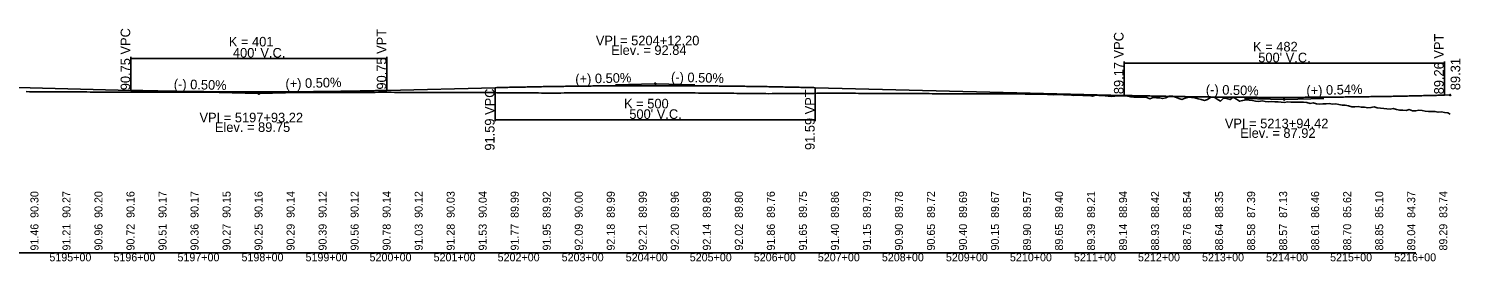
# Model space of a CAD drawing. Extents: x 2121671 to 2169879, y 557274 to 599957.
# Drawn here: x 2149002 to 2151237, y 582173 to 582537 of the extents above; entities that cross this region are included whole.
import ezdxf

# ---------------------------------------------------------------- set-up
doc = ezdxf.new("R2010")
doc.units = 0
for name, color, linetype in [('RD_DDB_GradeTX', 7, 'Continuous'), ('RD_DDB_Profile_EX', 7, 'Continuous'), ('RD_DDB_Profile_Lbl', 7, 'Continuous'), ('RD_DDB_Profile_PR', 7, 'Continuous'), ('RD_DDB_StaTX', 7, 'Continuous'), ('RD_DDB_StripGrade', 7, 'Continuous'), ('RD_DDB_VCLbl', 7, 'Continuous'), ('RD_GPK_Profile_Cell', 7, 'Continuous')]:
    doc.layers.add(name, color=color, linetype=linetype)

msp = doc.modelspace()

# ---------------------------------------------------------------- linework, layer by layer
at = {"layer": 'RD_DDB_GradeTX'}
for p, q in [((2149299.2, 582437.1), (2149360.2, 582435.6)), ((2149423.1, 582437.1), (2149362.2, 582435.6)), ((2149918.2, 582449.5), (2149979.1, 582451)), ((2150042.1, 582449.5), (2149981.1, 582451)), ((2150900.4, 582428), (2150961.4, 582426.5)), ((2151024.3, 582428.1), (2150963.4, 582426.5))]:
    msp.add_line(p, q, dxfattribs=at)
for centre in [(2149361.2, 582435.6), (2149980.1, 582451), (2150962.4, 582426.4), (2151221.5, 582433.4)]:
    msp.add_circle(centre, 1, dxfattribs=at)
at = {"layer": 'RD_DDB_Profile_EX'}
for points in [[(2148997.7, 582438.6), (2149002.7, 582438.5), (2149007.7, 582438.5), (2149012.7, 582438.4), (2149017.7, 582438.4), (2149022.7, 582438.3), (2149027.7, 582438.2), (2149032.7, 582438.2), (2149037.7, 582438.1), (2149042.7, 582438.1), (2149047.7, 582438.1), (2149052.7, 582438.1), (2149057.7, 582438.2), (2149062.7, 582438.2), (2149067.7, 582438.2), (2149072.7, 582438.2), (2149077.7, 582438.2), (2149082.7, 582438.2), (2149087.7, 582438.1), (2149092.7, 582438.1), (2149097.7, 582438), (2149102.7, 582438), (2149107.7, 582437.9), (2149112.7, 582437.9), (2149117.7, 582437.8), (2149122.7, 582437.8), (2149127.7, 582437.8), (2149132.7, 582437.8), (2149137.7, 582437.7), (2149142.7, 582437.7), (2149147.7, 582437.7), (2149152.7, 582437.7), (2149157.7, 582437.7), (2149162.7, 582437.6), (2149167.7, 582437.7), (2149172.7, 582437.7), (2149177.7, 582437.7), (2149182.7, 582437.7), (2149187.7, 582437.7), (2149192.7, 582437.7), (2149197.7, 582437.7), (2149202.7, 582437.7), (2149207.7, 582437.7), (2149212.7, 582437.7), (2149217.7, 582437.7), (2149222.7, 582437.7), (2149227.7, 582437.7)], [(2149227.7, 582437.7), (2149232.7, 582437.7), (2149237.7, 582437.7), (2149242.7, 582437.7), (2149247.7, 582437.7), (2149252.7, 582437.7), (2149257.7, 582437.7), (2149262.7, 582437.7), (2149267.7, 582437.7), (2149272.7, 582437.7), (2149277.7, 582437.7), (2149282.7, 582437.7), (2149287.7, 582437.7), (2149292.7, 582437.6), (2149297.7, 582437.6), (2149302.7, 582437.6), (2149307.7, 582437.6), (2149312.7, 582437.6), (2149317.7, 582437.6), (2149322.7, 582437.6), (2149327.7, 582437.6), (2149332.7, 582437.6), (2149337.7, 582437.6), (2149342.7, 582437.6), (2149347.7, 582437.6), (2149352.7, 582437.6), (2149357.7, 582437.6), (2149362.7, 582437.6), (2149367.7, 582437.7), (2149372.7, 582437.7), (2149377.7, 582437.7), (2149382.7, 582437.7), (2149387.7, 582437.7), (2149392.7, 582437.7), (2149397.7, 582437.7), (2149402.7, 582437.6), (2149407.7, 582437.6), (2149412.7, 582437.5), (2149417.7, 582437.5), (2149422.7, 582437.5), (2149427.7, 582437.5), (2149432.7, 582437.4), (2149437.7, 582437.4), (2149442.7, 582437.4), (2149447.7, 582437.4), (2149452.7, 582437.5), (2149457.7, 582437.5), (2149462.7, 582437.4), (2149467.7, 582437.4), (2149472.7, 582437.4), (2149477.7, 582437.4), (2149482.7, 582437.4), (2149487.7, 582437.4), (2149492.7, 582437.4), (2149497.7, 582437.4), (2149502.7, 582437.4), (2149507.7, 582437.4), (2149512.7, 582437.4), (2149517.7, 582437.4), (2149522.7, 582437.4), (2149527.7, 582437.4), (2149532.7, 582437.5), (2149537.7, 582437.5), (2149542.7, 582437.5), (2149547.7, 582437.6), (2149552.7, 582437.6), (2149557.7, 582437.6), (2149562.7, 582437.6), (2149567.7, 582437.6), (2149572.7, 582437.5), (2149577.7, 582437.5), (2149582.7, 582437.5), (2149587.7, 582437.5), (2149592.7, 582437.5), (2149597.7, 582437.5), (2149602.7, 582437.5), (2149607.7, 582437.4), (2149612.7, 582437.5), (2149617.7, 582437.4), (2149622.7, 582437.4), (2149627.7, 582437.4), (2149632.7, 582437.3), (2149637.7, 582437.3), (2149642.7, 582437.3), (2149647.7, 582437.2), (2149652.7, 582437), (2149657.7, 582437), (2149662.7, 582437), (2149667.7, 582437), (2149672.7, 582437), (2149677.7, 582437.1), (2149682.7, 582437), (2149687.7, 582437), (2149692.7, 582437.1), (2149697.7, 582437.1), (2149702.7, 582437.1), (2149707.7, 582437), (2149712.7, 582437), (2149717.7, 582437.1), (2149722.7, 582437), (2149727.7, 582437)], [(2149727.7, 582437), (2149732.7, 582436.9), (2149737.7, 582436.9), (2149742.7, 582436.8), (2149747.7, 582436.8), (2149752.7, 582436.8), (2149757.7, 582436.8), (2149762.7, 582436.8), (2149767.7, 582436.8), (2149772.7, 582436.6), (2149777.7, 582436.6), (2149782.7, 582436.5), (2149787.7, 582436.5), (2149792.7, 582436.5), (2149797.7, 582436.5), (2149802.7, 582436.4), (2149807.7, 582436.4), (2149812.7, 582436.4), (2149817.7, 582436.4), (2149822.7, 582436.4), (2149827.7, 582436.4), (2149832.7, 582436.4), (2149837.7, 582436.5), (2149842.7, 582436.7), (2149847.7, 582436.7), (2149852.7, 582436.7), (2149857.7, 582436.7), (2149862.7, 582436.7), (2149867.7, 582436.8), (2149872.7, 582436.8), (2149877.7, 582436.8), (2149882.7, 582436.8), (2149887.7, 582436.7), (2149892.7, 582436.7), (2149897.7, 582436.7), (2149902.7, 582436.7), (2149907.7, 582436.6), (2149912.7, 582436.6), (2149917.7, 582436.8), (2149922.7, 582436.8), (2149927.7, 582436.9), (2149932.7, 582436.9), (2149937.7, 582436.9), (2149942.7, 582436.9), (2149947.7, 582436.8), (2149952.7, 582436.8), (2149957.7, 582436.8), (2149962.7, 582436.8), (2149967.7, 582436.8), (2149972.7, 582436.8), (2149977.7, 582436.8), (2149982.7, 582436.8), (2149987.7, 582436.7), (2149992.7, 582436.6), (2149997.7, 582436.6), (2150002.7, 582436.6), (2150007.7, 582436.7), (2150012.7, 582436.7), (2150017.7, 582436.6), (2150022.7, 582436.6), (2150027.7, 582436.7), (2150032.7, 582436.8), (2150037.7, 582436.7), (2150042.7, 582436.5), (2150047.7, 582436.4), (2150052.7, 582436.4), (2150057.7, 582436.4), (2150062.7, 582436.3), (2150067.7, 582436.3), (2150072.7, 582436.3), (2150077.7, 582436.2), (2150082.7, 582436.2), (2150087.7, 582436.2), (2150092.7, 582436.1), (2150097.7, 582436.1), (2150102.7, 582436), (2150107.7, 582435.9), (2150112.7, 582435.9), (2150117.7, 582435.8), (2150122.7, 582435.6), (2150127.7, 582435.6), (2150132.7, 582435.6), (2150137.7, 582435.6), (2150142.7, 582435.5), (2150147.7, 582435.5), (2150152.7, 582435.5), (2150157.7, 582435.4), (2150162.7, 582435.6), (2150167.7, 582435.6), (2150172.7, 582435.6), (2150177.7, 582435.6), (2150182.7, 582435.5), (2150187.7, 582435.7), (2150192.7, 582435.8), (2150197.7, 582435.7), (2150202.7, 582435.7), (2150207.7, 582435.6), (2150212.7, 582435.6), (2150217.7, 582435.6), (2150222.7, 582435.9), (2150227.7, 582435.9)], [(2150227.7, 582435.9), (2150232.7, 582436), (2150237.7, 582436.1), (2150242.7, 582436.2), (2150247.7, 582436.2), (2150252.7, 582436.2), (2150257.7, 582436.2), (2150262.7, 582436.2), (2150267.7, 582436.1), (2150272.7, 582436.1), (2150277.7, 582436.1), (2150282.7, 582436), (2150287.7, 582436), (2150292.7, 582436), (2150297.7, 582435.9), (2150302.7, 582435.9), (2150307.7, 582435.9), (2150312.7, 582435.8), (2150317.7, 582435.8), (2150322.7, 582435.7), (2150327.7, 582435.7), (2150332.7, 582435.7), (2150337.7, 582435.7), (2150342.7, 582435.7), (2150347.7, 582435.7), (2150352.7, 582435.8), (2150357.7, 582435.7), (2150362.7, 582435.7), (2150367.7, 582435.7), (2150372.7, 582435.7), (2150377.7, 582435.7), (2150382.7, 582435.7), (2150387.7, 582435.7), (2150392.7, 582435.7), (2150397.7, 582435.6), (2150402.7, 582435.6), (2150407.7, 582435.5), (2150412.7, 582435.4), (2150417.7, 582435.4), (2150422.7, 582435.4), (2150427.7, 582435.3), (2150432.7, 582435.3), (2150437.7, 582435.3), (2150442.7, 582435.2), (2150447.7, 582435.2), (2150452.7, 582435.2), (2150457.7, 582435.2), (2150462.7, 582435.3), (2150467.7, 582435.3), (2150472.7, 582435.3), (2150477.7, 582435.3), (2150482.7, 582435.3), (2150487.7, 582435.3), (2150492.7, 582435.2), (2150497.7, 582435.2), (2150502.7, 582435.2), (2150507.7, 582435.2), (2150512.7, 582435.2), (2150517.7, 582435.2), (2150522.7, 582435.2), (2150527.7, 582435.2), (2150532.7, 582435.2), (2150537.7, 582435.3), (2150542.7, 582435.3), (2150547.7, 582435.2), (2150552.7, 582435), (2150557.7, 582434.9), (2150562.7, 582434.8), (2150567.7, 582434.7), (2150572.7, 582434.5), (2150577.7, 582434.6), (2150582.7, 582434.5), (2150587.7, 582434.4), (2150592.7, 582434.2), (2150597.7, 582434.1), (2150602.7, 582433.6), (2150607.7, 582433.9), (2150612.7, 582433.9), (2150617.7, 582433.8), (2150622.7, 582433.8), (2150627.7, 582433.8), (2150632.7, 582432.8), (2150637.7, 582433), (2150642.7, 582432.9), (2150647.7, 582432.8), (2150652.7, 582432.7), (2150657.7, 582432.6), (2150662.7, 582431.7), (2150667.7, 582432.9), (2150672.7, 582432.7), (2150677.7, 582432.5), (2150682.7, 582432.3), (2150687.7, 582431.3), (2150692.7, 582430.9), (2150697.7, 582431.7), (2150702.7, 582432), (2150707.7, 582431.9), (2150712.7, 582431.9), (2150717.7, 582431.6), (2150722.7, 582430.3), (2150727.7, 582430.2)], [(2150727.7, 582430.2), (2150732.7, 582430.2), (2150737.7, 582430.1), (2150742.7, 582430), (2150747.7, 582429.7), (2150752.7, 582427.3), (2150757.7, 582429.2), (2150762.7, 582429.1), (2150767.7, 582429), (2150772.7, 582427.8), (2150777.7, 582428.8), (2150782.7, 582431.4), (2150787.7, 582431.3), (2150792.7, 582430), (2150797.7, 582427.7), (2150802.7, 582426.4), (2150807.7, 582428.2), (2150812.7, 582430.1), (2150817.7, 582429.6), (2150822.7, 582428.7), (2150827.7, 582427.5), (2150832.7, 582426.3), (2150837.7, 582424.9), (2150842.7, 582426.5), (2150847.7, 582430.1), (2150852.7, 582430), (2150857.7, 582426.8), (2150862.7, 582423.9), (2150867.7, 582428.6), (2150872.7, 582427.9), (2150877.7, 582426.3), (2150882.7, 582430), (2150887.7, 582426.8), (2150892.7, 582423.7), (2150897.7, 582424.9), (2150902.7, 582425.7), (2150907.7, 582425.5), (2150912.7, 582424.8), (2150917.7, 582423.8), (2150922.7, 582423.3), (2150927.7, 582424), (2150932.7, 582423), (2150937.7, 582422.5), (2150942.7, 582423), (2150947.7, 582422.9), (2150952.7, 582422.9), (2150957.7, 582422.4), (2150962.7, 582421.8), (2150967.7, 582422.5), (2150972.7, 582422), (2150977.7, 582422.2), (2150982.7, 582422.2), (2150987.7, 582422.3), (2150992.7, 582421.9), (2150997.7, 582421.6), (2151002.7, 582420.2), (2151007.7, 582421.3), (2151012.7, 582419.7), (2151017.7, 582419.1), (2151022.7, 582419.4), (2151027.7, 582419.8), (2151032.7, 582420), (2151037.7, 582419.1), (2151042.7, 582419.5), (2151047.7, 582418.6), (2151052.7, 582417.7), (2151057.7, 582417.4), (2151062.7, 582416.4), (2151067.7, 582414.9), (2151072.7, 582415), (2151077.7, 582415.2), (2151082.7, 582414.4), (2151087.7, 582414.3), (2151092.7, 582413.5), (2151097.7, 582413.7), (2151102.7, 582414.7), (2151107.7, 582413.5), (2151112.7, 582413), (2151117.7, 582412.4), (2151122.7, 582411.7), (2151127.7, 582411.4), (2151132.7, 582412), (2151137.7, 582410.8), (2151142.7, 582409.5), (2151147.7, 582409.4), (2151152.7, 582409.3), (2151157.7, 582410.6), (2151162.7, 582408.8), (2151167.7, 582408.6), (2151172.7, 582409.5), (2151177.7, 582408.9), (2151182.7, 582408.1), (2151187.7, 582407.7), (2151192.7, 582407.4), (2151197.7, 582407.8), (2151202.7, 582406.5), (2151207.7, 582407.1), (2151212.7, 582406), (2151217.7, 582405.6), (2151221.5, 582403.5)]]:
    msp.add_lwpolyline(points, dxfattribs=at)
at = {"layer": 'RD_DDB_Profile_PR'}
for p, q in [((2148964.4, 582445.5), (2149161.2, 582440.6)), ((2149561.2, 582440.6), (2149730.1, 582444.8)), ((2150230.1, 582444.8), (2150712.4, 582432.7)), ((2151212.4, 582433.1), (2151221.5, 582433.4))]:
    msp.add_line(p, q, dxfattribs=at)
for points in [[(2149161.2, 582440.6), (2149169.2, 582440.4), (2149177.2, 582440.2), (2149185.2, 582440), (2149193.2, 582439.8), (2149201.2, 582439.7), (2149209.2, 582439.5), (2149217.2, 582439.4), (2149225.2, 582439.2), (2149233.2, 582439.1), (2149241.2, 582439), (2149249.2, 582438.9), (2149257.2, 582438.7), (2149265.2, 582438.6), (2149273.2, 582438.6), (2149281.2, 582438.5), (2149289.2, 582438.4), (2149297.2, 582438.3), (2149305.2, 582438.3), (2149313.2, 582438.2), (2149321.2, 582438.2), (2149329.2, 582438.1), (2149337.2, 582438.1), (2149345.2, 582438.1), (2149353.2, 582438.1), (2149361.2, 582438.1), (2149369.2, 582438.1), (2149377.2, 582438.1), (2149385.2, 582438.1), (2149393.2, 582438.1), (2149401.2, 582438.2), (2149409.2, 582438.2), (2149417.2, 582438.3), (2149425.2, 582438.3), (2149433.2, 582438.4), (2149441.2, 582438.5), (2149449.2, 582438.6), (2149457.2, 582438.6), (2149465.2, 582438.7), (2149473.2, 582438.9), (2149481.2, 582439), (2149489.2, 582439.1), (2149497.2, 582439.2), (2149505.2, 582439.4), (2149513.2, 582439.5), (2149521.2, 582439.7), (2149529.2, 582439.8), (2149537.2, 582440), (2149545.2, 582440.2), (2149553.2, 582440.4), (2149561.2, 582440.6)], [(2149730.1, 582444.8), (2149740.1, 582445), (2149750.1, 582445.3), (2149760.1, 582445.5), (2149770.1, 582445.7), (2149780.1, 582445.9), (2149790.1, 582446.1), (2149800.1, 582446.3), (2149810.1, 582446.5), (2149820.1, 582446.6), (2149830.1, 582446.8), (2149840.1, 582446.9), (2149850.1, 582447.1), (2149860.1, 582447.2), (2149870.1, 582447.3), (2149880.1, 582447.4), (2149890.1, 582447.5), (2149900.1, 582447.6), (2149910.1, 582447.7), (2149920.1, 582447.7), (2149930.1, 582447.8), (2149940.1, 582447.8), (2149950.1, 582447.9), (2149960.1, 582447.9), (2149970.1, 582447.9), (2149980.1, 582447.9), (2149990.1, 582447.9), (2150000.1, 582447.9), (2150010.1, 582447.9), (2150020.1, 582447.8), (2150030.1, 582447.8), (2150040.1, 582447.7), (2150050.1, 582447.7), (2150060.1, 582447.6), (2150070.1, 582447.5), (2150080.1, 582447.4), (2150090.1, 582447.3), (2150100.1, 582447.2), (2150110.1, 582447.1), (2150120.1, 582446.9), (2150130.1, 582446.8), (2150140.1, 582446.6), (2150150.1, 582446.5), (2150160.1, 582446.3), (2150170.1, 582446.1), (2150180.1, 582445.9), (2150190.1, 582445.7), (2150200.1, 582445.5), (2150210.1, 582445.2), (2150220.1, 582445), (2150230.1, 582444.8)], [(2150712.4, 582432.7), (2150722.4, 582432.4), (2150732.4, 582432.2), (2150742.4, 582432), (2150752.4, 582431.8), (2150762.4, 582431.6), (2150772.4, 582431.4), (2150782.4, 582431.2), (2150792.4, 582431), (2150802.4, 582430.9), (2150812.4, 582430.7), (2150822.4, 582430.6), (2150832.4, 582430.4), (2150842.4, 582430.3), (2150852.4, 582430.2), (2150862.4, 582430.1), (2150872.4, 582430), (2150882.4, 582429.9), (2150892.4, 582429.9), (2150902.4, 582429.8), (2150912.4, 582429.8), (2150922.4, 582429.7), (2150932.4, 582429.7), (2150942.4, 582429.7), (2150952.4, 582429.7), (2150962.4, 582429.7), (2150972.4, 582429.7), (2150982.4, 582429.7), (2150992.4, 582429.7), (2151002.4, 582429.8), (2151012.4, 582429.8), (2151022.4, 582429.9), (2151032.4, 582430), (2151042.4, 582430.1), (2151052.4, 582430.2), (2151062.4, 582430.3), (2151072.4, 582430.4), (2151082.4, 582430.5), (2151092.4, 582430.7), (2151102.4, 582430.8), (2151112.4, 582431), (2151122.4, 582431.1), (2151132.4, 582431.3), (2151142.4, 582431.5), (2151152.4, 582431.7), (2151162.4, 582431.9), (2151172.4, 582432.1), (2151182.4, 582432.4), (2151192.4, 582432.6), (2151202.4, 582432.9), (2151212.4, 582433.1)]]:
    msp.add_spline(points, degree=3, dxfattribs=at)
at = {"layer": 'RD_DDB_VCLbl'}
for p, q in [((2149161.2, 582493.1), (2149161.2, 582440.6)), ((2149161.2, 582490.6), (2149561.2, 582490.6)), ((2149561.2, 582493.1), (2149561.2, 582440.6)), ((2150712.4, 582485.6), (2150712.4, 582432.7)), ((2150712.4, 582483.1), (2151212.4, 582483.1)), ((2151212.4, 582485.6), (2151212.4, 582433.1)), ((2149730.1, 582392.3), (2149730.1, 582444.8)), ((2150230.1, 582392.3), (2150230.1, 582444.8)), ((2149730.1, 582394.8), (2150230.1, 582394.8))]:
    msp.add_line(p, q, dxfattribs=at)
at = {"layer": 'RD_GPK_Profile_Cell'}
msp.add_line((2146667.9, 582186.8), (2151167.9, 582186.8), dxfattribs=at)

# ---------------------------------------------------------------- texts
at = {"layer": 'RD_DDB_GradeTX'}
for s, rotation, p in [('(-) 0.50%', 358.5698, (2149228.1, 582443.1)), ('(+) 0.50%', 1.4298, (2149402.7, 582443.6)), ('(+) 0.50%', 1.4298, (2149855.4, 582450.9)), ('(-) 0.50%', 358.5653, (2150004.6, 582454.1)), ('(-) 0.50%', 358.5653, (2150839.8, 582434.6)), ('(+) 0.54%', 1.5363, (2150997.1, 582432.8))]:
    msp.add_text(s, height=15, rotation=rotation, dxfattribs=at).set_placement(p)
at = {"layer": 'RD_DDB_Profile_Lbl'}
for s, p in [('VPI = 5204+12.20', (2149887.3, 582511)), ('Elev. = 92.84', (2149911.3, 582496)), ('VPI = 5197+93.22', (2149268.4, 582390.6)), ('VPI = 5213+94.42', (2150869.6, 582381.4)), ('Elev. = 89.75', (2149292.4, 582375.6)), ('Elev. = 87.92', (2150893.6, 582366.4))]:
    msp.add_text(s, height=15, dxfattribs=at).set_placement(p)
msp.add_text('89.31', height=15, rotation=90, dxfattribs=at).set_placement((2151237.2, 582440.9))
at = {"layer": 'RD_DDB_StaTX'}
for s, p in [('5195+00', (2149034, 582173.5)), ('5196+00', (2149134, 582173.5)), ('5197+00', (2149234, 582173.5)), ('5198+00', (2149334, 582173.5)), ('5199+00', (2149434, 582173.5)), ('5200+00', (2149534, 582173.5)), ('5201+00', (2149634, 582173.5)), ('5202+00', (2149734, 582173.5)), ('5203+00', (2149834, 582173.5)), ('5204+00', (2149934, 582173.5)), ('5205+00', (2150034, 582173.5)), ('5206+00', (2150134, 582173.5)), ('5207+00', (2150234, 582173.5)), ('5208+00', (2150334, 582173.5)), ('5209+00', (2150434, 582173.5)), ('5210+00', (2150534, 582173.5)), ('5211+00', (2150634, 582173.5)), ('5212+00', (2150734, 582173.5)), ('5213+00', (2150834, 582173.5)), ('5214+00', (2150934, 582173.5)), ('5215+00', (2151034, 582173.5)), ('5216+00', (2151134, 582173.5))]:
    msp.add_text(s, height=12.5, dxfattribs=at).set_placement(p)
at = {"layer": 'RD_DDB_StripGrade'}
for s, height, p in [('90.75 VPC', 15, (2149160.2, 582440.8)), ('90.75 VPT', 15, (2149560.2, 582441.8)), ('89.17 VPC', 15, (2150711.4, 582434.7)), ('89.26 VPT', 15, (2151211.4, 582434.4)), ('91.59 VPC', 15, (2149729.1, 582346.4)), ('91.59 VPT', 15, (2150229.1, 582347.4)), ('90.30', 12.5, (2149016.9, 582241.3)), ('90.27', 12.5, (2149066.9, 582241.3)), ('90.20', 12.5, (2149116.9, 582241.3)), ('90.16', 12.5, (2149166.9, 582241.3)), ('90.17', 12.5, (2149216.9, 582241.3)), ('90.17', 12.5, (2149266.9, 582241.3)), ('90.15', 12.5, (2149316.9, 582241.3)), ('90.16', 12.5, (2149366.9, 582241.3)), ('90.14', 12.5, (2149416.9, 582241.3)), ('90.12', 12.5, (2149466.9, 582241.3)), ('90.12', 12.5, (2149516.9, 582241.3)), ('90.14', 12.5, (2149566.9, 582241.3)), ('90.12', 12.5, (2149616.9, 582241.3)), ('90.03', 12.5, (2149666.9, 582241.3)), ('90.04', 12.5, (2149716.9, 582241.3)), ('89.99', 12.5, (2149766.9, 582241.3)), ('89.92', 12.5, (2149816.9, 582241.3)), ('90.00', 12.5, (2149866.9, 582241.3)), ('89.99', 12.5, (2149916.9, 582241.3)), ('89.99', 12.5, (2149966.9, 582241.3)), ('89.96', 12.5, (2150016.9, 582241.3)), ('89.89', 12.5, (2150066.9, 582241.3)), ('89.80', 12.5, (2150116.9, 582241.3)), ('89.76', 12.5, (2150166.9, 582241.3)), ('89.75', 12.5, (2150216.9, 582241.3)), ('89.86', 12.5, (2150266.9, 582241.3)), ('89.79', 12.5, (2150316.9, 582241.3)), ('89.78', 12.5, (2150366.9, 582241.3)), ('89.72', 12.5, (2150416.9, 582241.3)), ('89.69', 12.5, (2150466.9, 582241.3)), ('89.67', 12.5, (2150516.9, 582241.3)), ('89.57', 12.5, (2150566.9, 582241.3)), ('89.40', 12.5, (2150616.9, 582241.3)), ('89.21', 12.5, (2150666.9, 582241.3)), ('88.94', 12.5, (2150716.9, 582241.3)), ('88.42', 12.5, (2150766.9, 582241.3)), ('88.54', 12.5, (2150816.9, 582241.3)), ('88.35', 12.5, (2150866.9, 582241.3)), ('87.39', 12.5, (2150916.9, 582241.3)), ('87.13', 12.5, (2150966.9, 582241.3)), ('86.46', 12.5, (2151016.9, 582241.3)), ('85.62', 12.5, (2151066.9, 582241.3)), ('85.10', 12.5, (2151116.9, 582241.3)), ('84.37', 12.5, (2151166.9, 582241.3)), ('83.74', 12.5, (2151216.9, 582241.3)), ('91.46', 12.5, (2149016.9, 582190.3)), ('91.21', 12.5, (2149066.9, 582190.3)), ('90.96', 12.5, (2149116.9, 582190.3)), ('90.72', 12.5, (2149166.9, 582190.3)), ('90.51', 12.5, (2149216.9, 582190.3)), ('90.36', 12.5, (2149266.9, 582190.3)), ('90.27', 12.5, (2149316.9, 582190.3)), ('90.25', 12.5, (2149366.9, 582190.3)), ('90.29', 12.5, (2149416.9, 582190.3)), ('90.39', 12.5, (2149466.9, 582190.3)), ('90.56', 12.5, (2149516.9, 582190.3)), ('90.78', 12.5, (2149566.9, 582190.3)), ('91.03', 12.5, (2149616.9, 582190.3)), ('91.28', 12.5, (2149666.9, 582190.3)), ('91.53', 12.5, (2149716.9, 582190.3)), ('91.77', 12.5, (2149766.9, 582190.3)), ('91.95', 12.5, (2149816.9, 582190.3)), ('92.09', 12.5, (2149866.9, 582190.3)), ('92.18', 12.5, (2149916.9, 582190.3)), ('92.21', 12.5, (2149966.9, 582190.3)), ('92.20', 12.5, (2150016.9, 582190.3)), ('92.14', 12.5, (2150066.9, 582190.3)), ('92.02', 12.5, (2150116.9, 582190.3)), ('91.86', 12.5, (2150166.9, 582190.3)), ('91.65', 12.5, (2150216.9, 582190.3)), ('91.40', 12.5, (2150266.9, 582190.3)), ('91.15', 12.5, (2150316.9, 582190.3)), ('90.90', 12.5, (2150366.9, 582190.3)), ('90.65', 12.5, (2150416.9, 582190.3)), ('90.40', 12.5, (2150466.9, 582190.3)), ('90.15', 12.5, (2150516.9, 582190.3)), ('89.90', 12.5, (2150566.9, 582190.3)), ('89.65', 12.5, (2150616.9, 582190.3)), ('89.39', 12.5, (2150666.9, 582190.3)), ('89.14', 12.5, (2150716.9, 582190.3)), ('88.93', 12.5, (2150766.9, 582190.3)), ('88.76', 12.5, (2150816.9, 582190.3)), ('88.64', 12.5, (2150866.9, 582190.3)), ('88.58', 12.5, (2150916.9, 582190.3)), ('88.57', 12.5, (2150966.9, 582190.3)), ('88.61', 12.5, (2151016.9, 582190.3)), ('88.70', 12.5, (2151066.9, 582190.3)), ('88.85', 12.5, (2151116.9, 582190.3)), ('89.04', 12.5, (2151166.9, 582190.3)), ('89.29', 12.5, (2151216.9, 582190.3))]:
    msp.add_text(s, height=height, rotation=90, dxfattribs=at).set_placement(p)
at = {"layer": 'RD_DDB_VCLbl'}
for s, p in [('K = 401', (2149314.2, 582509.2)), ("400' V.C.", (2149320.6, 582491.8)), ('K = 482', (2150913.7, 582501.4)), ("500' V.C.", (2150921.8, 582484.4)), ('K = 500', (2149931.4, 582412.4)), ("500' V.C.", (2149939.6, 582396))]:
    msp.add_text(s, height=15, dxfattribs=at).set_placement(p)

doc.saveas('drawing.dxf')
